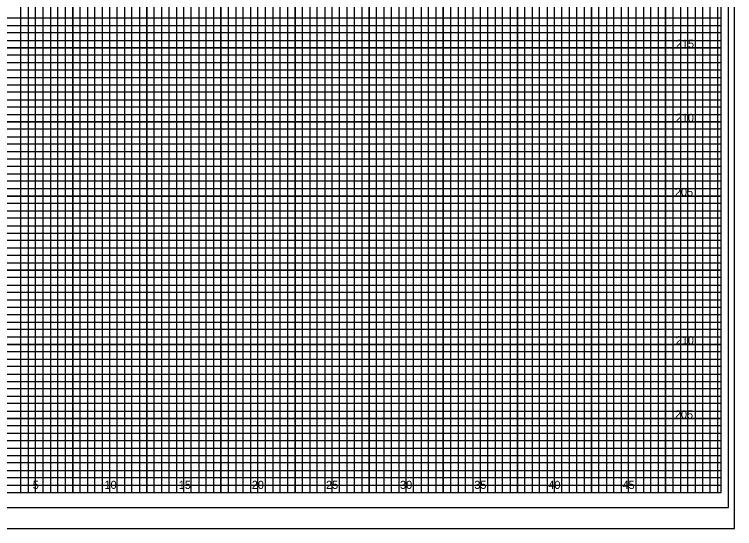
# Model space of a CAD drawing. Extents: x -4 to 103, y -2 to 209.
# Drawn here: x 54.82 to 103.4, y 139.22 to 173.9 of the extents above; entities that cross this region are included whole.
import ezdxf

# ---------------------------------------------------------------- set-up
doc = ezdxf.new("R2010")
doc.units = 0
for name, color, linetype in [('Old_Level_10', 7, 'Continuous'), ('Old_Level_16', 7, 'Continuous'), ('Old_Level_17', 7, 'Continuous'), ('Old_Level_3', 7, 'Continuous'), ('Old_Level_5', 7, 'Continuous'), ('Old_Level_6', 7, 'Continuous'), ('Old_Level_8', 7, 'Continuous'), ('Prop Dimension', 7, 'Continuous'), ('Typical Curb CELL', 7, 'Continuous')]:
    doc.layers.add(name, color=color, linetype=linetype)

msp = doc.modelspace()

# ---------------------------------------------------------------- linework, layer by layer
at = {"layer": 'Old_Level_10'}
for p, q in [((56.25, 141.65), (56.25, 206.65)), ((58.75, 141.65), (58.75, 206.65)), ((61.25, 141.65), (61.25, 206.65)), ((63.75, 141.65), (63.75, 206.65)), ((66.25, 141.65), (66.25, 206.65)), ((68.75, 141.65), (68.75, 206.65)), ((71.25, 141.65), (71.25, 206.65)), ((73.75, 141.65), (73.75, 206.65)), ((91.25, 141.65), (91.25, 205.075)), ((93.75, 141.65), (93.75, 205.075)), ((96.25, 141.65), (96.25, 205.075)), ((98.75, 141.65), (98.75, 205.075)), ((101.25, 141.65), (101.25, 205.075)), ((76.25, 141.65), (76.25, 203.65)), ((78.75, 141.65), (78.75, 203.65)), ((81.25, 141.65), (81.25, 203.65)), ((83.75, 141.65), (83.75, 203.65)), ((86.25, 141.65), (86.25, 203.65)), ((88.75, 141.65), (88.75, 203.65)), ((0, 171.65), (102.5, 171.65)), ((0, 169.15), (102.5, 169.15)), ((0, 166.65), (102.5, 166.65)), ((0, 164.15), (102.5, 164.15)), ((0, 161.65), (102.5, 161.65)), ((0, 159.15), (102.5, 159.15)), ((0, 156.65), (102.5, 156.65)), ((0, 154.15), (102.5, 154.15)), ((0, 151.65), (102.5, 151.65)), ((0, 149.15), (102.5, 149.15)), ((0, 146.65), (102.5, 146.65)), ((0, 144.15), (102.5, 144.15))]:
    msp.add_line(p, q, dxfattribs=at)
at = {"layer": 'Old_Level_17'}
for points in [[(54.75, 141.65), (55.25, 141.65), (55.25, 206.65)], [(55.75, 206.65), (55.75, 141.65), (56.75, 141.65), (56.75, 206.65)], [(57.25, 206.65), (57.25, 141.65), (57.75, 141.65), (57.75, 206.65)], [(58.25, 206.65), (58.25, 141.65), (59.25, 141.65), (59.25, 206.65)], [(59.75, 206.65), (59.75, 141.65), (60.25, 141.65), (60.25, 206.65)], [(60.75, 206.65), (60.75, 141.65), (61.75, 141.65), (61.75, 206.65)], [(62.25, 206.65), (62.25, 141.65), (62.75, 141.65), (62.75, 206.65)], [(63.25, 206.65), (63.25, 141.65), (64.25, 141.65), (64.25, 206.65)], [(64.75, 206.65), (64.75, 141.65), (65.25, 141.65), (65.25, 206.65)], [(65.75, 206.65), (65.75, 141.65), (66.75, 141.65), (66.75, 206.65)], [(67.25, 206.65), (67.25, 141.65), (67.75, 141.65), (67.75, 206.65)], [(68.25, 206.65), (68.25, 141.65), (69.25, 141.65), (69.25, 206.65)], [(69.75, 206.65), (69.75, 141.65), (70.25, 141.65), (70.25, 206.65)], [(70.75, 206.65), (70.75, 141.65), (71.75, 141.65), (71.75, 206.65)], [(72.25, 206.65), (72.25, 141.65), (72.75, 141.65), (72.75, 206.65)], [(73.25, 206.65), (73.25, 141.65), (74.25, 141.65), (74.25, 203.65)], [(89.75, 203.65), (89.75, 141.65), (90.25, 141.65), (90.25, 205.075)], [(90.75, 205.075), (90.75, 141.65), (91.75, 141.65), (91.75, 205.075)], [(92.25, 205.075), (92.25, 141.65), (92.75, 141.65), (92.75, 205.075)], [(93.25, 205.075), (93.25, 141.65), (94.25, 141.65), (94.25, 205.075)], [(94.75, 205.075), (94.75, 141.65), (95.25, 141.65), (95.25, 205.075)], [(95.75, 205.075), (95.75, 141.65), (96.75, 141.65), (96.75, 205.075)], [(97.25, 205.075), (97.25, 141.65), (97.75, 141.65), (97.75, 205.075)], [(98.25, 205.075), (98.25, 141.65), (99.25, 141.65), (99.25, 205.075)], [(99.75, 205.075), (99.75, 141.65), (100.25, 141.65), (100.25, 205.075)], [(100.25, 205.075), (100.75, 205.075), (100.75, 141.65), (101.75, 141.65), (101.75, 205.075), (102.25, 205.075), (102.25, 141.65)], [(74.75, 203.65), (74.75, 141.65), (75.25, 141.65), (75.25, 203.65)], [(75.75, 203.65), (75.75, 141.65), (76.75, 141.65), (76.75, 203.65)], [(77.25, 203.65), (77.25, 141.65), (77.75, 141.65), (77.75, 203.65)], [(78.25, 203.65), (78.25, 141.65), (79.25, 141.65), (79.25, 203.65)], [(79.75, 203.65), (79.75, 141.65), (80.25, 141.65), (80.25, 203.65)], [(80.75, 203.65), (80.75, 141.65), (81.75, 141.65), (81.75, 203.65)], [(82.25, 203.65), (82.25, 141.65), (82.75, 141.65), (82.75, 203.65)], [(83.25, 203.65), (83.25, 141.65), (84.25, 141.65), (84.25, 203.65)], [(84.75, 203.65), (84.75, 141.65), (85.25, 141.65), (85.25, 203.65)], [(85.75, 203.65), (85.75, 141.65), (86.75, 141.65), (86.75, 203.65)], [(87.25, 203.65), (87.25, 141.65), (87.75, 141.65), (87.75, 203.65)], [(88.25, 203.65), (88.25, 141.65), (89.25, 141.65), (89.25, 203.65)], [(0, 173.15), (102.5, 173.15), (102.5, 173.65), (0, 173.65)], [(0, 172.15), (102.5, 172.15), (102.5, 172.65), (0, 172.65)], [(0, 170.65), (102.5, 170.65), (102.5, 171.15), (0, 171.15)], [(0, 169.65), (102.5, 169.65), (102.5, 170.15), (0, 170.15)], [(0, 168.15), (102.5, 168.15), (102.5, 168.65), (0, 168.65)], [(0, 167.15), (102.5, 167.15), (102.5, 167.65), (0, 167.65)], [(0, 165.65), (102.5, 165.65), (102.5, 166.15), (0, 166.15)], [(0, 164.65), (102.5, 164.65), (102.5, 165.15), (0, 165.15)], [(0, 163.15), (102.5, 163.15), (102.5, 163.65), (0, 163.65)], [(0, 162.15), (102.5, 162.15), (102.5, 162.65), (0, 162.65)], [(0, 160.65), (102.5, 160.65), (102.5, 161.15), (0, 161.15)], [(0, 159.65), (102.5, 159.65), (102.5, 160.15), (0, 160.15)], [(0, 158.15), (102.5, 158.15), (102.5, 158.65), (0, 158.65)], [(0, 157.15), (102.5, 157.15), (102.5, 157.65), (0, 157.65)], [(0, 155.65), (102.5, 155.65), (102.5, 156.15), (0, 156.15)], [(0, 154.65), (102.5, 154.65), (102.5, 155.15), (0, 155.15)], [(0, 153.15), (102.5, 153.15), (102.5, 153.65), (0, 153.65)], [(0, 152.15), (102.5, 152.15), (102.5, 152.65), (0, 152.65)], [(0, 150.65), (102.5, 150.65), (102.5, 151.15), (0, 151.15)], [(0, 149.65), (102.5, 149.65), (102.5, 150.15), (0, 150.15)], [(0, 148.15), (102.5, 148.15), (102.5, 148.65), (0, 148.65)], [(0, 147.15), (102.5, 147.15), (102.5, 147.65), (0, 147.65)], [(0, 145.65), (102.5, 145.65), (102.5, 146.15), (0, 146.15)], [(0, 144.65), (102.5, 144.65), (102.5, 145.15), (0, 145.15)], [(0, 143.15), (102.5, 143.15), (102.5, 143.65), (0, 143.65)], [(0, 142.15), (102.5, 142.15), (102.5, 142.65), (0, 142.65)]]:
    msp.add_lwpolyline(points, dxfattribs=at)
at = {"layer": 'Old_Level_3'}
msp.add_line((-3.5, 139.225), (103.4, 139.225), dxfattribs=at)
at = {"layer": 'Old_Level_5'}
msp.add_lwpolyline([(103.4, 209.05), (-3.5, 209.05), (-3.5, 139.225), (103.4, 139.225)], close=True, dxfattribs=at)
at = {"layer": 'Old_Level_6'}
msp.add_lwpolyline([(102.5, 206.65), (0, 206.65), (0, 141.65), (102.5, 141.65)], close=True, dxfattribs=at)
at = {"layer": 'Old_Level_8'}
for points in [[(56.25, 141.65), (56.25, 206.65)], [(58.75, 206.65), (58.75, 141.65), (61.25, 141.65), (61.25, 206.65)], [(63.75, 206.65), (63.75, 141.65), (66.25, 141.65), (66.25, 206.65)], [(68.75, 206.65), (68.75, 141.65), (71.25, 141.65), (71.25, 206.65)], [(73.75, 206.65), (73.75, 141.65), (76.25, 141.65), (76.25, 203.65)], [(88.75, 203.65), (88.75, 141.65), (91.25, 141.65), (91.25, 205.075)], [(93.75, 205.075), (93.75, 141.65), (96.25, 141.65), (96.25, 205.075)], [(98.75, 205.075), (98.75, 141.65), (101.25, 141.65), (101.25, 205.075)], [(78.75, 203.65), (78.75, 141.65), (81.25, 141.65), (81.25, 203.65)], [(83.75, 203.65), (83.75, 141.65), (86.25, 141.65), (86.25, 203.65)], [(0, 169.15), (102.5, 169.15), (102.5, 171.65), (0, 171.65)], [(0, 164.15), (102.5, 164.15), (102.5, 166.65), (0, 166.65)], [(0, 159.15), (102.5, 159.15), (102.5, 161.65), (0, 161.65)], [(0, 154.15), (102.5, 154.15), (102.5, 156.65), (0, 156.65)], [(0, 149.15), (102.5, 149.15), (102.5, 151.65), (0, 151.65)], [(0, 144.15), (102.5, 144.15), (102.5, 146.65), (0, 146.65)]]:
    msp.add_lwpolyline(points, dxfattribs=at)
at = {"layer": 'Typical Curb CELL'}
msp.add_lwpolyline([(103, 207.65), (-2.8, 207.65), (-2.8, 140.65), (103, 140.65)], close=True, dxfattribs=at)

# ---------------------------------------------------------------- texts
at = {"layer": 'Old_Level_16'}
for s, p in [('5', (56.0574, 141.9)), ('10', (60.8971, 141.9)), ('15', (65.9057, 141.9)), ('20', (70.8312, 141.9)), ('25', (75.8399, 141.9)), ('30', (80.8312, 141.9)), ('35', (85.8399, 141.9)), ('40', (90.8313, 141.9)), ('45', (95.8399, 141.9))]:
    msp.add_text(s, height=0.55, dxfattribs=at).set_placement(p)
at = {"layer": 'Prop Dimension'}
for s, p in [('215', (99.4383, 171.65)), ('210', (99.4296, 166.65)), ('205', (99.3724, 161.65)), ('210', (99.4296, 151.65)), ('205', (99.3724, 146.65))]:
    msp.add_text(s, height=0.55, dxfattribs=at).set_placement(p)

doc.saveas('drawing.dxf')
